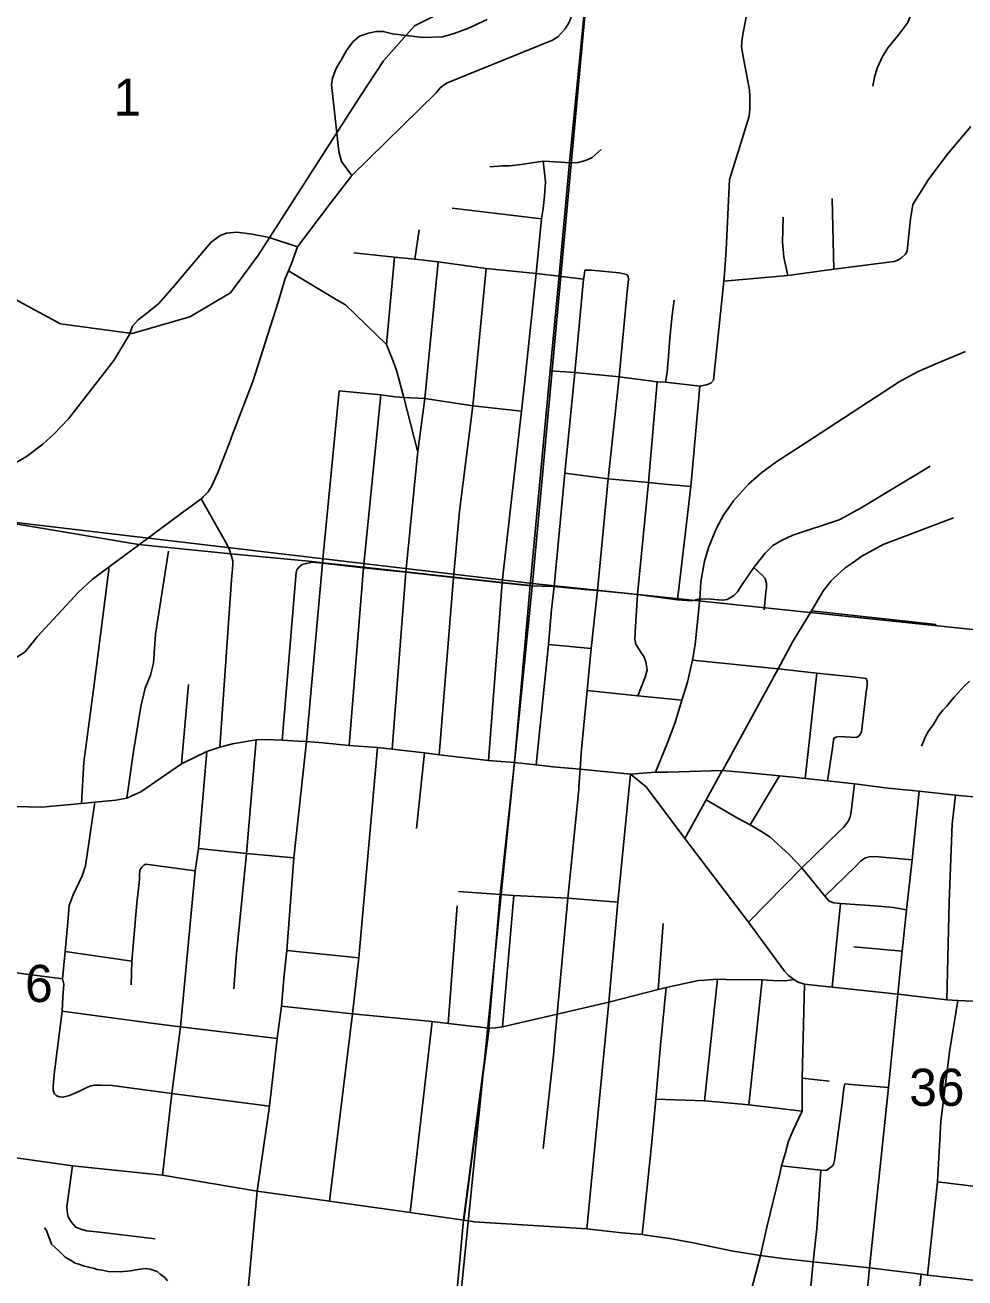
# Model space of a CAD drawing. Extents: x 0 to 34, y -2 to 22.
# Drawn here: x 6.678 to 7.738, y 16.795 to 18.207 of the extents above; entities that cross this region are included whole.
import ezdxf

# ---------------------------------------------------------------- set-up
doc = ezdxf.new("R2010")
doc.units = 0
for name, color, linetype in [('GM_X_City_Street', 7, 'Continuous'), ('GM_X_County_Road', 7, 'Continuous'), ('GM_X_Minor_River', 7, 'Continuous'), ('GM_X_Rail_Line', 7, 'Continuous'), ('GM_X_Section', 7, 'Continuous'), ('GM_X_Section_Text', 7, 'Continuous'), ('GM_X_State_Route', 7, 'Continuous')]:
    doc.layers.add(name, color=color, linetype=linetype)

msp = doc.modelspace()

# ---------------------------------------------------------------- linework, layer by layer
at = {"layer": 'GM_X_City_Street'}
for p, q in [((7.5903, 17.932), (7.5883, 18.012)), ((7.16, 18.0008), (7.2605, 17.989)), ((7.1177, 17.9433), (7.1226, 17.9767)), ((7.0861, 17.8473), (7.0948, 17.9456)), ((7.5649, 17.5468), (7.7057, 17.5317)), ((7.2684, 17.5089), (7.3167, 17.5044)), ((7.5578, 17.3581), (7.5712, 17.4766)), ((6.8547, 17.3743), (6.8627, 17.464)), ((7.1198, 17.3017), (7.1287, 17.3868)), ((7.496, 17.3055), (7.5289, 17.361)), ((7.2166, 17.078), (7.2296, 17.226)), ((7.1556, 17.0816), (7.1655, 17.2145)), ((7.5884, 17.1226), (7.5979, 17.2171)), ((7.3921, 17.1201), (7.3978, 17.1945)), ((6.7238, 17.1629), (6.7989, 17.152)), ((6.9735, 17.164), (7.0546, 17.1558)), ((7.6126, 17.168), (7.6673, 17.1631)), ((7.4446, 16.9944), (7.4591, 17.1316)), ((7.4943, 16.99), (7.5093, 17.1308)), ((7.0217, 16.8813), (7.0477, 17.0925)), ((7.1127, 16.8685), (7.1373, 17.0838)), ((7.5546, 17.0201), (7.5851, 17.0168))]:
    msp.add_line(p, q, dxfattribs=at)
for points in [[(7.4547, 17.807), (7.4663, 17.9186), (7.4671, 17.9271), (7.4687, 17.9539), (7.4725, 18.0332), (7.4859, 18.0754), (7.4948, 18.1048), (7.4956, 18.1127), (7.4956, 18.1256), (7.4952, 18.1345), (7.493, 18.1461), (7.4875, 18.174), (7.486, 18.1833), (7.4869, 18.1917), (7.4881, 18.1992), (7.4932, 18.2258), (7.4989, 18.2557), (7.5073, 18.3032)], [(7.0467, 18.0378), (7.0353, 18.0534), (7.0322, 18.0648), (7.024, 18.1405), (7.0251, 18.1476), (7.028, 18.1558), (7.0308, 18.1615), (7.0347, 18.1678), (7.041, 18.1788), (7.0485, 18.1888), (7.0554, 18.1947), (7.0657, 18.1983), (7.0743, 18.2002), (7.0823, 18.2003), (7.0925, 18.1975), (7.1268, 18.1932), (7.1489, 18.1941), (7.1623, 18.1979), (7.1783, 18.204), (7.1995, 18.2138)], [(7.4663, 17.9186), (7.5384, 17.9251), (7.5903, 17.932), (7.6582, 17.941), (7.6604, 17.9416), (7.6635, 17.9429), (7.6669, 17.9452), (7.6708, 17.9489), (7.6721, 17.9509), (7.6728, 17.953), (7.6765, 17.989), (7.6792, 18.0052), (7.6968, 18.0333), (7.7178, 18.0613), (7.7446, 18.093)], [(7.2024, 18.0476), (7.2164, 18.0486), (7.2246, 18.0485), (7.2376, 18.0501), (7.2624, 18.054), (7.2826, 18.0529), (7.2926, 18.0521), (7.302, 18.0525), (7.3076, 18.0539), (7.312, 18.0553), (7.3177, 18.0582), (7.3278, 18.0672)], [(7.2009, 17.3782), (7.2163, 17.5785), (7.2173, 17.5894), (7.238, 17.7721), (7.2414, 17.8024), (7.2548, 17.9272), (7.2605, 17.989), (7.2624, 18.0007), (7.264, 18.0145), (7.265, 18.0308), (7.2624, 18.054)], [(7.5384, 17.9251), (7.534, 17.9457), (7.5324, 17.9628), (7.533, 17.9909)], [(7.0489, 17.9507), (7.0948, 17.9456), (7.1177, 17.9433), (7.1441, 17.9405), (7.1983, 17.933), (7.2548, 17.9272), (7.2807, 17.9244), (7.3081, 17.921)], [(7.1212, 17.727), (7.1292, 17.7862), (7.1441, 17.9405)], [(7.0924, 17.391), (7.1076, 17.5904), (7.1212, 17.727), (7.1206, 17.7289), (7.1054, 17.7875), (7.0977, 17.8168), (7.0935, 17.8285), (7.0861, 17.8473), (7.0397, 17.8918), (7.0311, 17.897), (6.9754, 17.9303)], [(7.1452, 17.3846), (7.1616, 17.5845), (7.1683, 17.6593), (7.1831, 17.7782), (7.1983, 17.933)], [(7.2546, 17.3733), (7.2684, 17.5089), (7.2719, 17.5485), (7.2748, 17.5745), (7.287, 17.7023), (7.2984, 17.8156), (7.3081, 17.921), (7.3086, 17.9252), (7.3096, 17.9309)], [(7.3029, 17.3486), (7.3042, 17.3684), (7.3052, 17.3869), (7.3121, 17.4573), (7.3167, 17.5044), (7.3237, 17.5698), (7.3357, 17.6956), (7.3378, 17.7132), (7.3481, 17.8108), (7.3576, 17.9109), (7.3583, 17.9169), (7.3586, 17.921), (7.3584, 17.9239), (7.3569, 17.9261)], [(7.3096, 17.9309), (7.3172, 17.931), (7.3481, 17.9281), (7.3569, 17.9261)], [(7.4101, 17.8973), (7.408, 17.8804), (7.4055, 17.8543), (7.404, 17.834), (7.4025, 17.8156), (7.4004, 17.8047)], [(7.2708, 17.8174), (7.2984, 17.8156), (7.3481, 17.8108), (7.3912, 17.8052), (7.4004, 17.8047), (7.4391, 17.8004), (7.4465, 17.8016), (7.4517, 17.8036), (7.4547, 17.807)], [(7.3912, 17.8052), (7.3811, 17.6917), (7.369, 17.5653)], [(7.414, 17.5595), (7.4289, 17.687), (7.4391, 17.8004)], [(6.9956, 17.3996), (7.0138, 17.6006), (7.0146, 17.6092), (7.0325, 17.7949)], [(7.0325, 17.7949), (7.0797, 17.7906), (7.0955, 17.7884), (7.1054, 17.7875), (7.1292, 17.7862), (7.1831, 17.7782), (7.238, 17.7721)], [(7.0437, 17.3953), (7.06, 17.5956), (7.0797, 17.7906)], [(7.287, 17.7023), (7.3357, 17.6956), (7.3811, 17.6917), (7.3998, 17.6896), (7.4289, 17.687)], [(7.4393, 17.5604), (7.4521, 17.5602), (7.4642, 17.5591), (7.47, 17.5599), (7.4745, 17.5623), (7.4774, 17.5641), (7.4816, 17.5683), (7.4863, 17.5754), (7.5002, 17.5959), (7.5129, 17.6118), (7.5163, 17.6154), (7.5216, 17.6205), (7.5313, 17.6264), (7.5439, 17.6324), (7.5961, 17.6496), (7.6028, 17.6531), (7.6211, 17.663), (7.6989, 17.71)], [(6.9118, 17.5891), (6.9128, 17.5997), (6.9126, 17.6034), (6.9117, 17.607), (6.9105, 17.6109), (6.9089, 17.6157), (6.9063, 17.6215), (6.8769, 17.6732)], [(7.4222, 17.2904), (7.4464, 17.3338), (7.4645, 17.3669), (7.4649, 17.3675), (7.5273, 17.4816), (7.5441, 17.5124), (7.5649, 17.5468), (7.5787, 17.5697), (7.5871, 17.5809), (7.5898, 17.5836), (7.603, 17.5955), (7.6107, 17.6008), (7.6217, 17.6085), (7.6457, 17.6217), (7.7253, 17.6517)], [(6.793, 17.3358), (6.8006, 17.3883), (6.809, 17.439), (6.8137, 17.4598), (6.8199, 17.4744), (6.8231, 17.4881), (6.8256, 17.5206), (6.84, 17.6143)], [(6.991, 17.5992), (7.0025, 17.6019), (7.0138, 17.6006), (7.06, 17.5956), (7.1076, 17.5904), (7.1616, 17.5845), (7.2163, 17.5785), (7.2482, 17.575), (7.2748, 17.5745), (7.3093, 17.5711), (7.3237, 17.5698), (7.369, 17.5653), (7.414, 17.5595), (7.4303, 17.5583), (7.4393, 17.5604)], [(6.7421, 17.3299), (6.7446, 17.3764), (6.7559, 17.461), (6.7732, 17.5964)], [(6.898, 17.3932), (6.9116, 17.5873), (6.9118, 17.5891)], [(6.9683, 17.4012), (6.9842, 17.5903), (6.9849, 17.593), (6.9859, 17.5948), (6.9871, 17.5962), (6.991, 17.5992)], [(7.5115, 17.5482), (7.5137, 17.5684), (7.5143, 17.5728), (7.5143, 17.578), (7.5127, 17.5834), (7.5096, 17.587), (7.5002, 17.5959)], [(7.3692, 17.4511), (7.3774, 17.4723), (7.3796, 17.4806), (7.3782, 17.4894), (7.3761, 17.4955), (7.3719, 17.5016), (7.3669, 17.5095), (7.3658, 17.5151), (7.3661, 17.5228), (7.369, 17.5653)], [(7.4309, 17.4913), (7.5273, 17.4816), (7.5712, 17.4766), (7.6149, 17.4722), (7.6265, 17.4708)], [(7.6158, 17.4042), (7.6187, 17.4062), (7.6214, 17.4104), (7.6268, 17.4552), (7.6277, 17.4629), (7.6277, 17.4675), (7.6265, 17.4708)], [(7.3121, 17.4573), (7.3692, 17.4511), (7.4189, 17.4464)], [(7.5832, 17.3553), (7.5886, 17.3922), (7.59, 17.4012), (7.5906, 17.4034), (7.5924, 17.4046), (7.596, 17.4053), (7.6158, 17.4042)], [(6.9139, 17.1207), (6.9163, 17.1566), (6.9281, 17.2735), (6.939, 17.4015)], [(7.0477, 17.0925), (7.0546, 17.1558), (7.0759, 17.3928)], [(6.8334, 16.9107), (6.844, 17.0028), (6.8536, 17.078), (6.8704, 17.254), (6.8741, 17.2791), (6.8833, 17.3883)], [(7.2764, 17.0722), (7.2782, 17.0924), (7.2905, 17.2229), (7.3027, 17.3456), (7.3029, 17.3486)], [(7.494, 17.1958), (7.5541, 17.2571), (7.597, 17.2989), (7.6014, 17.3032), (7.6021, 17.3041), (7.6066, 17.3102), (7.6088, 17.3148), (7.6099, 17.3204), (7.6134, 17.352)], [(7.6723, 17.2097), (7.6573, 17.2125), (7.6361, 17.2144), (7.5979, 17.2171), (7.5903, 17.2178), (7.5851, 17.2197), (7.5801, 17.2253), (7.5541, 17.2571), (7.5402, 17.2719), (7.5181, 17.292), (7.5079, 17.2986), (7.496, 17.3055), (7.4824, 17.313), (7.4464, 17.3338)], [(7.6208, 16.7039), (7.6305, 16.8061), (7.6519, 17.0096), (7.6625, 17.1149), (7.6673, 17.1631), (7.6723, 17.2097), (7.6784, 17.2661), (7.6863, 17.3438)], [(7.7176, 17.1085), (7.7201, 17.2187), (7.7237, 17.3066), (7.7274, 17.3393)], [(6.7135, 17.0004), (6.7116, 17.0023), (6.7107, 17.0043), (6.7102, 17.0066), (6.7101, 17.0092), (6.7103, 17.0115), (6.7118, 17.0276), (6.7202, 17.0955), (6.7211, 17.1114), (6.7223, 17.1261), (6.7208, 17.1322), (6.7238, 17.1629), (6.7266, 17.1959), (6.7283, 17.2148), (6.7328, 17.2268), (6.743, 17.2481), (6.7464, 17.2594), (6.7572, 17.3314)], [(6.8741, 17.2791), (6.9281, 17.2735), (6.9816, 17.2685)], [(7.5801, 17.2253), (7.6142, 17.2584), (7.6208, 17.2651), (7.6258, 17.2684), (7.6306, 17.2696), (7.637, 17.2698), (7.6784, 17.2661)], [(6.798, 17.1254), (6.7989, 17.152), (6.8046, 17.2173), (6.8074, 17.2439), (6.8074, 17.2487), (6.8077, 17.2547)], [(6.8077, 17.2547), (6.8101, 17.258), (6.8119, 17.26), (6.813, 17.2607), (6.8145, 17.2612), (6.8704, 17.254)], [(7.1671, 17.2304), (7.2144, 17.2271), (7.2296, 17.226), (7.2905, 17.2229), (7.3468, 17.2184)], [(6.3175, 17.1819), (6.349, 17.1777), (6.5011, 17.161), (6.5927, 17.1487), (6.7208, 17.1322)], [(6.9675, 17.1013), (7.0477, 17.0925), (7.1373, 17.0838), (7.1556, 17.0816), (7.2015, 17.0763), (7.2086, 17.0767), (7.2166, 17.078), (7.2782, 17.0924), (7.3365, 17.1059), (7.3921, 17.1201), (7.4012, 17.1223), (7.4378, 17.1301), (7.4445, 17.1307), (7.4591, 17.1316), (7.4685, 17.1312), (7.5093, 17.1308), (7.5213, 17.1303)], [(7.374, 16.8439), (7.3847, 16.9443), (7.3895, 16.9964), (7.3948, 17.0572), (7.4012, 17.1223)], [(7.3952, 16.2431), (7.4169, 16.3509), (7.4324, 16.4422), (7.4685, 16.5369), (7.4715, 16.5488), (7.4913, 16.7438), (7.4923, 16.7556), (7.4943, 16.7707), (7.5074, 16.8201), (7.5148, 16.8521), (7.5294, 16.9123), (7.5314, 16.9213), (7.5357, 16.9362), (7.5392, 16.9489), (7.5442, 16.9615), (7.5505, 16.9743), (7.5547, 16.9827), (7.5547, 16.9956), (7.5546, 17.0201), (7.5573, 17.126)], [(7.5213, 17.1303), (7.5358, 17.1297), (7.545, 17.1313)], [(7.6957, 16.7979), (7.7069, 16.9033), (7.7108, 16.9713), (7.7206, 17.0499), (7.7299, 17.1075)], [(6.7202, 17.0955), (6.8268, 17.0813), (6.8536, 17.078), (6.9627, 17.0648)], [(7.1732, 16.8598), (7.1822, 16.9288), (7.2015, 17.0763)], [(7.2627, 16.9409), (7.2742, 17.0459), (7.2764, 17.0722)], [(6.7135, 17.0004), (6.7152, 16.9996), (6.7176, 16.9989), (6.7211, 16.9985), (6.7284, 17.0005), (6.7357, 17.0035), (6.7398, 17.0053), (6.7459, 17.0083), (6.7488, 17.01), (6.7528, 17.0115), (6.7566, 17.0121), (6.7634, 17.0123), (6.7766, 17.0118), (6.844, 17.0028), (6.9541, 16.9885)], [(7.5839, 16.9175), (7.5857, 16.9188), (7.588, 16.9206), (7.5899, 16.9229), (7.5911, 16.9272), (7.6001, 16.9947), (7.6008, 17.0028), (7.6017, 17.0105), (7.6028, 17.0136)], [(7.6028, 17.0136), (7.6138, 17.0126), (7.6519, 17.0096)], [(7.3895, 16.9964), (7.4446, 16.9944), (7.4661, 16.9925), (7.4943, 16.99), (7.5547, 16.9827)], [(6.7321, 16.9211), (6.7256, 16.8755), (6.7259, 16.8698), (6.7271, 16.8637), (6.7305, 16.858), (6.7355, 16.8521), (6.7414, 16.8497), (6.7478, 16.8479), (6.7628, 16.8465), (6.8252, 16.839)], [(7.5314, 16.9213), (7.5754, 16.9165), (7.5806, 16.916), (7.5817, 16.9162), (7.5822, 16.9165), (7.5839, 16.9175)], [(7.5615, 16.7575), (7.5671, 16.8129), (7.5712, 16.8506), (7.5754, 16.9165)], [(7.7069, 16.9033), (7.7563, 16.8973), (7.7663, 16.8959)], [(7.6664, 16.5759), (7.6671, 16.6032), (7.669, 16.6144), (7.6709, 16.6349), (7.6888, 16.7991)]]:
    msp.add_lwpolyline(points, dxfattribs=at)
at = {"layer": 'GM_X_County_Road'}
for p, q in [((7.3468, 17.2184), (7.361, 17.3629)), ((7.361, 17.3629), (7.3893, 17.365)), ((7.3365, 17.1059), (7.3468, 17.2184)), ((7.3118, 16.85), (7.3365, 17.1059))]:
    msp.add_line(p, q, dxfattribs=at)
for points in [[(6.9856, 17.9573), (7.0226, 18.0067), (7.0467, 18.0378), (7.1418, 18.131), (7.1464, 18.1366), (7.1534, 18.1418), (7.2731, 18.1903), (7.2789, 18.194), (7.2874, 18.2033), (7.291, 18.209), (7.2937, 18.2153), (7.2974, 18.2376), (7.2976, 18.2388), (7.3044, 18.2759), (7.3107, 18.324), (7.3167, 18.3587), (7.3199, 18.3688), (7.3256, 18.3884)], [(6.8159, 17.8826), (6.8167, 17.8832), (6.8175, 17.8839), (6.8291, 17.8935), (6.847, 17.9139), (6.8877, 17.9621), (6.8985, 17.9702), (6.9054, 17.9727), (6.9172, 17.9739), (6.9345, 17.9715), (6.9537, 17.968), (6.9856, 17.9573)], [(6.9128, 17.7468), (6.9354, 17.8054), (6.9639, 17.8949), (6.9718, 17.9216), (6.9754, 17.9303), (6.9787, 17.9385), (6.9856, 17.9573)], [(6.5676, 17.6628), (6.5724, 17.6631), (6.5734, 17.6632), (6.5814, 17.6657), (6.5967, 17.6721), (6.6802, 17.7211), (6.6984, 17.735), (6.7108, 17.7461), (6.7275, 17.7635), (6.7785, 17.8292), (6.7963, 17.8587), (6.7996, 17.8681), (6.8059, 17.8752), (6.8159, 17.8826)], [(7.3893, 17.365), (7.4019, 17.3963), (7.4114, 17.4212), (7.4189, 17.4464), (7.4251, 17.4664), (7.4309, 17.4913), (7.434, 17.509), (7.4393, 17.5604), (7.4403, 17.5796), (7.4445, 17.603), (7.4492, 17.619), (7.4579, 17.6403), (7.4658, 17.6548), (7.4771, 17.6711), (7.4939, 17.6897), (7.5091, 17.7028), (7.526, 17.7152), (7.5493, 17.7302), (7.6639, 17.805), (7.6844, 17.8166), (7.7072, 17.8263), (7.7388, 17.8395)], [(6.8886, 17.6871), (6.8891, 17.6879), (6.8959, 17.7029), (6.9088, 17.7364), (6.9128, 17.7468)], [(6.8769, 17.6732), (6.8781, 17.6741), (6.8794, 17.6755), (6.8847, 17.6812), (6.8886, 17.6871)], [(6.8209, 17.6318), (6.8561, 17.6579), (6.8769, 17.6732)], [(6.5712, 17.4014), (6.5922, 17.4306), (6.6083, 17.4518), (6.6175, 17.4595), (6.6365, 17.4734), (6.6592, 17.4884), (6.6785, 17.5008), (6.6922, 17.5178), (6.7382, 17.5675), (6.7541, 17.5822), (6.7732, 17.5964), (6.8065, 17.6211), (6.8209, 17.6318)], [(6.9101, 16.6067), (6.9137, 16.6365), (6.9205, 16.6895), (6.9257, 16.7372), (6.9402, 16.8926), (6.9541, 16.9885), (6.9627, 17.0648), (6.9675, 17.1013), (6.9705, 17.1364), (6.9735, 17.164), (6.9816, 17.2685), (6.9956, 17.3996)], [(7.361, 17.3629), (7.3786, 17.3487), (7.4222, 17.2904), (7.494, 17.1958), (7.5345, 17.1408), (7.5392, 17.1359), (7.545, 17.1313), (7.5501, 17.1282), (7.5573, 17.126), (7.5884, 17.1226), (7.6625, 17.1149), (7.7176, 17.1085), (7.7299, 17.1075), (7.7634, 17.1063)], [(6.1634, 17.0422), (6.1975, 17.0377), (6.3328, 17.0201), (6.4086, 17.0103), (6.4146, 17.0082), (6.4225, 17.0046), (6.496, 16.9536), (6.5046, 16.95), (6.5109, 16.9485), (6.5233, 16.9463), (6.5411, 16.9442), (6.5892, 16.9384), (6.6735, 16.9296), (6.7321, 16.9211), (6.8334, 16.9107), (6.9402, 16.8926), (7.0217, 16.8813), (7.091, 16.8716), (7.1127, 16.8685), (7.1732, 16.8598), (7.1827, 16.8585)], [(7.1827, 16.8585), (7.1846, 16.8582), (7.3118, 16.85), (7.3513, 16.8458), (7.374, 16.8439), (7.3861, 16.8421), (7.4025, 16.8396)], [(7.4025, 16.8396), (7.4054, 16.8392), (7.4318, 16.8345), (7.4767, 16.8251), (7.5074, 16.8201), (7.5322, 16.8169), (7.5671, 16.8129), (7.6305, 16.8061), (7.6888, 16.7991), (7.6957, 16.7979), (7.7437, 16.7928), (7.806, 16.7861), (7.8851, 16.7752)]]:
    msp.add_lwpolyline(points, dxfattribs=at)
at = {"layer": 'GM_X_Minor_River'}
for points in [[(7.6803, 18.3439), (7.6758, 18.3341), (7.6729, 18.3243), (7.6787, 18.3119), (7.6837, 18.2981), (7.6884, 18.2866), (7.69, 18.2763), (7.6901, 18.2645), (7.6852, 18.2502), (7.6815, 18.2377), (7.6784, 18.2226), (7.6736, 18.2101), (7.6634, 18.1967), (7.6516, 18.1821), (7.6449, 18.172), (7.6389, 18.1589), (7.636, 18.1487), (7.6342, 18.1384)], [(7.7433, 17.4678), (7.7371, 17.4619), (7.7304, 17.4545), (7.7257, 17.4497), (7.7214, 17.4445), (7.7175, 17.4396), (7.7132, 17.4348), (7.708, 17.4281), (7.7025, 17.4187), (7.6973, 17.412), (7.6933, 17.4045), (7.6913, 17.3996), (7.6889, 17.3943)], [(6.8389, 16.7915), (6.836, 16.7954), (6.8308, 16.7989), (6.8274, 16.8021), (6.8241, 16.8033), (6.8195, 16.8046), (6.8142, 16.8055), (6.8081, 16.8049), (6.8035, 16.8039), (6.7978, 16.8029), (6.7894, 16.802), (6.7856, 16.8017), (6.7723, 16.8021), (6.7655, 16.8034), (6.7598, 16.8044), (6.7568, 16.8056), (6.7455, 16.8082), (6.7379, 16.8107), (6.7349, 16.8115), (6.7297, 16.8147), (6.7237, 16.8183), (6.7167, 16.8254), (6.7126, 16.8289), (6.7081, 16.8328), (6.7028, 16.8482), (6.7002, 16.8513)]]:
    msp.add_lwpolyline(points, dxfattribs=at)
at = {"layer": 'GM_X_Rail_Line'}
for points in [[(5.905, 17.7117), (6.0414, 17.7045), (6.1028, 17.7012), (6.1352, 17.7013), (6.1907, 17.6999), (6.238, 17.6988), (6.3473, 17.6853), (6.5625, 17.6629), (6.8063, 17.6216), (6.9103, 17.6114), (7.0022, 17.6024), (7.0136, 17.6012), (7.0598, 17.5961), (7.1074, 17.5909), (7.1613, 17.585), (7.216, 17.579), (7.2479, 17.5755), (7.2705, 17.818), (7.2805, 17.9249), (7.2924, 18.0527), (7.3254, 18.3889)], [(7.3254, 18.3889), (7.2924, 18.0527), (7.2805, 17.9249), (7.2705, 17.818), (7.2479, 17.5755), (7.2301, 17.3765), (7.2142, 17.2276), (7.2013, 17.0768), (7.1819, 16.9294), (7.1729, 16.8603), (7.1419, 16.5212), (7.1299, 16.384), (7.1117, 16.189), (7.0415, 15.3869), (7.041, 15.3813), (7.0162, 15.1361), (7.0052, 15.0295), (7.018, 15.0319), (7.3068, 15.0956), (7.4995, 15.1593), (7.5948, 15.214), (7.6912, 15.289), (7.9856, 15.5639)], [(7.2061, 18.251), (7.1174, 18.2066), (7.0826, 18.167), (7.0573, 18.1289), (6.9417, 17.9483), (6.91, 17.9055), (6.8641, 17.8786), (6.7992, 17.8596), (6.7184, 17.8707), (6.671, 17.896), (6.6045, 17.942), (6.4604, 18.1226), (6.4177, 18.167), (6.3781, 18.1955), (6.3337, 18.2177)], [(7.1419, 16.5212), (7.1729, 16.8603), (7.1819, 16.9294), (7.2013, 17.0768), (7.2142, 17.2276), (7.2301, 17.3765), (7.2479, 17.5755), (7.216, 17.579), (7.1613, 17.585), (7.1074, 17.5909), (7.0598, 17.5961), (7.0136, 17.6012), (7.0022, 17.6024), (6.9103, 17.6114), (6.8063, 17.6216), (6.5625, 17.6629), (6.3473, 17.6853), (6.238, 17.6988), (6.1907, 17.6999), (6.1352, 17.7013), (6.1028, 17.7012), (6.0414, 17.7045), (5.905, 17.7117)]]:
    msp.add_lwpolyline(points, dxfattribs=at)
at = {"layer": 'GM_X_Section'}
for points in [[(7.3433, 18.5849), (7.2505, 17.5778), (6.241, 17.6971), (6.3407, 18.6907)], [(8.3344, 18.4751), (8.2288, 17.4754), (7.2505, 17.5778), (7.3433, 18.5849)], [(6.241, 17.6971), (7.2505, 17.5778), (7.1499, 16.5781), (6.1288, 16.703)], [(7.2505, 17.5778), (8.2288, 17.4754), (8.1243, 16.4653), (7.1499, 16.5781)]]:
    msp.add_lwpolyline(points, close=True, dxfattribs=at)
at = {"layer": 'GM_X_State_Route'}
msp.add_line((7.361, 17.3629), (7.3893, 17.365), dxfattribs=at)
for points in [[(6.6659, 17.3262), (6.6974, 17.3257), (6.7421, 17.3299), (6.7572, 17.3314), (6.7809, 17.3336), (6.793, 17.3358), (6.7982, 17.3379), (6.809, 17.343), (6.8547, 17.3743), (6.8833, 17.3883), (6.898, 17.3932), (6.9124, 17.3971), (6.939, 17.4015), (6.9503, 17.402), (6.9683, 17.4012), (6.9865, 17.4002)], [(6.9865, 17.4002), (6.9956, 17.3996), (7.014, 17.3982), (7.0437, 17.3953), (7.0759, 17.3928), (7.0924, 17.391), (7.1287, 17.3868), (7.1452, 17.3846), (7.2009, 17.3782)], [(7.2009, 17.3782), (7.215, 17.3771), (7.2303, 17.376), (7.2546, 17.3733), (7.2734, 17.3711), (7.3042, 17.3684), (7.361, 17.3629)], [(7.3893, 17.365), (7.403, 17.3649), (7.4645, 17.3669), (7.4857, 17.3649)], [(7.4857, 17.3649), (7.4984, 17.3638), (7.5289, 17.361), (7.5483, 17.3589), (7.5578, 17.3581), (7.5832, 17.3553), (7.6134, 17.352), (7.6513, 17.3472), (7.6863, 17.3438), (7.7274, 17.3393), (7.7594, 17.3362)]]:
    msp.add_lwpolyline(points, dxfattribs=at)

# ---------------------------------------------------------------- texts
at = {"layer": 'GM_X_Section_Text'}
for s, height, p in [('1', 0.0419, (6.7781, 18.1051)), ('6', 0.0419, (6.6785, 17.1059)), ('36', 0.04186, (7.6752, 16.9888))]:
    msp.add_text(s, height=height, rotation=0, dxfattribs=at).set_placement(p)

doc.saveas('drawing.dxf')
